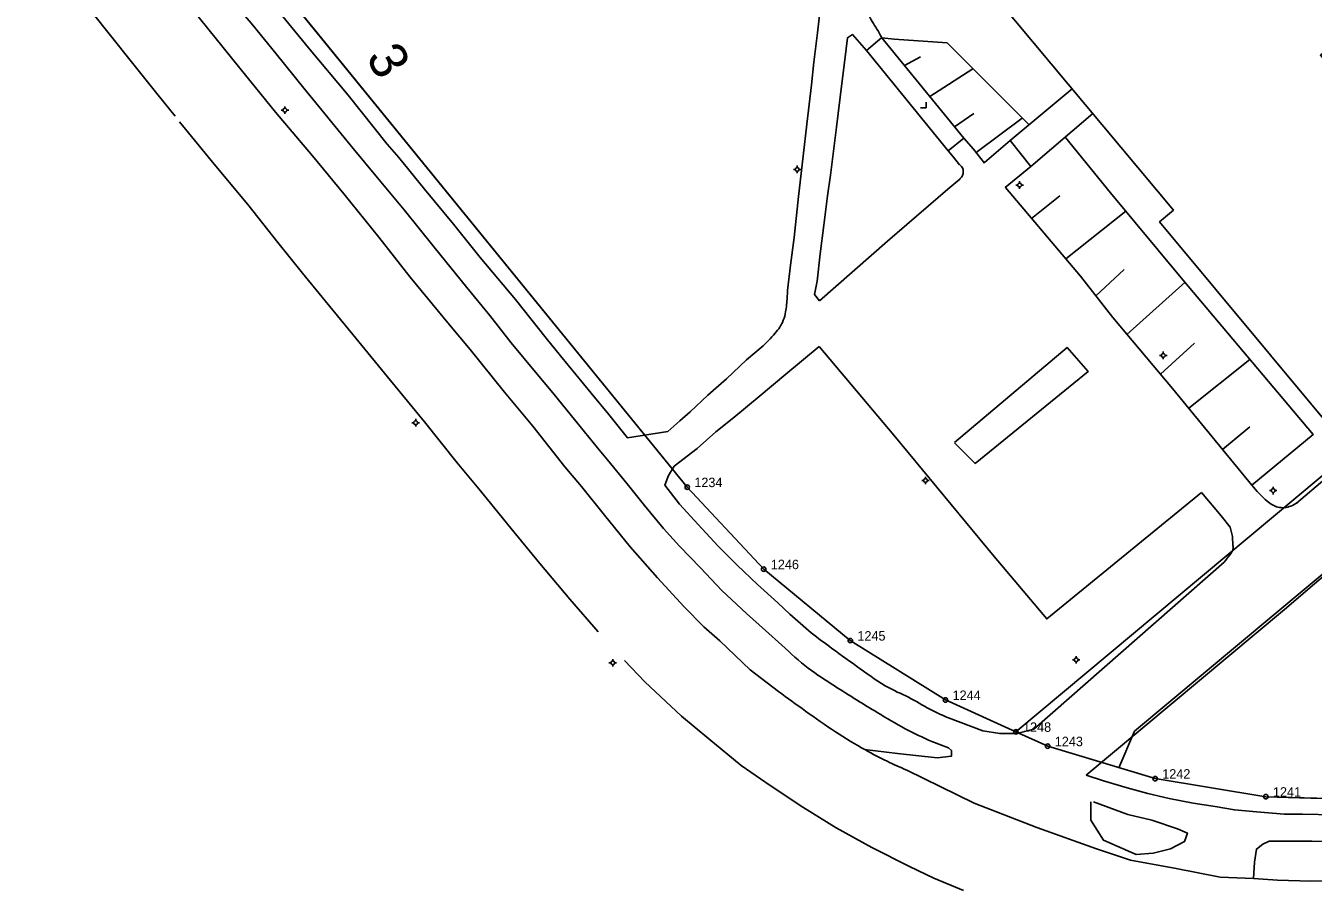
# Model space of a CAD drawing. Extents: x 1517693 to 1518189, y 6494860 to 6495280.
# Drawn here: x 1517702.4 to 1517838.6, y 6494947.3 to 6495038.2 of the extents above; entities that cross this region are included whole.
import ezdxf

# ---------------------------------------------------------------- set-up
doc = ezdxf.new("R2010")
doc.units = 0
for name, color, linetype in [('adress', 7, 'Continuous'), ('allmanbyggnad', 7, 'Continuous'), ('bro', 7, 'Continuous'), ('gc_vag', 7, 'Continuous'), ('grans', 7, 'Continuous'), ('granspunkt', 7, 'Continuous'), ('granspunkt_text', 7, 'Continuous'), ('kvartersgrans', 7, 'Continuous'), ('parkeringskant', 7, 'Continuous'), ('rattighet_grans_ANV_EJ', 7, 'Continuous'), ('slant_skraffering', 7, 'Continuous'), ('slantfot', 7, 'Continuous'), ('stodmur', 7, 'Continuous'), ('stolpe_belysning', 7, 'Continuous'), ('trappa', 7, 'Continuous'), ('trappsymbol', 7, 'Continuous'), ('vagkant', 7, 'Continuous'), ('vagkant_mindre', 7, 'Continuous')]:
    doc.layers.add(name, color=color, linetype=linetype)

msp = doc.modelspace()

# ---------------------------------------------------------------- linework, layer by layer
at = {"layer": 'allmanbyggnad'}
msp.add_lwpolyline([(1517795.98, 6495052.03), (1517837.72, 6495086.69), (1517844.24, 6495078.9), (1517844.89, 6495079.4), (1517856.96, 6495064.93), (1517856.28, 6495064.33), (1517862.19, 6495057.11), (1517842.98, 6495041.23), (1517844.57, 6495039.29), (1517839.38, 6495035.07), (1517847.33, 6495025.71), (1517853.22, 6495030.6), (1517862.35, 6495019.75), (1517850.98, 6495010.13), (1517853.38, 6495007.24), (1517840.06, 6494996.19), (1517822.37, 6495017.44), (1517823.84, 6495018.69), (1517795.97, 6495052.03)], dxfattribs=at)
at = {"layer": 'bro'}
msp.add_lwpolyline([(1517813.13, 6495031.51), (1517806.55, 6495026.04), (1517808.74, 6495023.31), (1517815.3, 6495028.91)], dxfattribs=at)
at = {"layer": 'gc_vag'}
for p, q in [((1517782.84, 6495001.34), (1517786.35, 6495004.25)), ((1517783.24, 6494975.95), (1517782, 6494977.16))]:
    msp.add_line(p, q, dxfattribs=at)
for points in [[(1517737.05, 6495025.22), (1517731.83, 6495031.58), (1517728.92, 6495035.22), (1517726.43, 6495038.23), (1517723.49, 6495041.77), (1517721.14, 6495044.68)], [(1517740.66, 6495025.65), (1517736.52, 6495030.84), (1517732.32, 6495035.85), (1517728.5, 6495040.55), (1517724.81, 6495044.99)], [(1517786.9, 6495043.91), (1517786.54, 6495040.51), (1517786.18, 6495037.43), (1517785.79, 6495034.34), (1517785.53, 6495031.93)], [(1517791.38, 6495035.56), (1517789.88, 6495037.27), (1517789.36, 6495036.91), (1517789.08, 6495034.58), (1517788.74, 6495032.09)], [(1517785.53, 6495031.93), (1517785.06, 6495027.78), (1517784.67, 6495024.39), (1517784.16, 6495020.11)], [(1517788.74, 6495032.09), (1517788.2, 6495027.45), (1517787.55, 6495022.39), (1517787.24, 6495020.21)], [(1517801.66, 6495026.31), (1517802.68, 6495025.15), (1517803.84, 6495023.66)], [(1517753.76, 6495004.65), (1517751.53, 6495007.54), (1517749.08, 6495010.52), (1517745.64, 6495014.76), (1517742.46, 6495018.72), (1517739.62, 6495022.1), (1517737.05, 6495025.22)], [(1517757.49, 6495005.15), (1517754.23, 6495009.22), (1517750.51, 6495013.67), (1517747.68, 6495017.21), (1517744.59, 6495020.89), (1517741.9, 6495024.25), (1517740.66, 6495025.65)], [(1517801.2, 6495023.49), (1517800.55, 6495024.28), (1517800, 6495024.96)], [(1517784.16, 6495020.11), (1517783.72, 6495015.78), (1517783.33, 6495012.85), (1517782.99, 6495010.18), (1517782.96, 6495009.28)], [(1517787.24, 6495020.21), (1517786.85, 6495017.1), (1517786.46, 6495014.07), (1517786.15, 6495011.19), (1517785.87, 6495009.77), (1517786.38, 6495009.1)], [(1517760.6, 6494996.36), (1517758.17, 6494999.37), (1517756.35, 6495001.55), (1517753.76, 6495004.65)], [(1517780.43, 6495004.32), (1517778.67, 6495002.85), (1517776.54, 6495000.85), (1517774.58, 6494999.13), (1517772.72, 6494997.34), (1517771.6, 6494996.4), (1517770.34, 6494995.28), (1517766.07, 6494994.61), (1517764.1, 6494997.06), (1517762.25, 6494999.31), (1517758.99, 6495003.29), (1517757.49, 6495005.15)], [(1517777.33, 6494996.75), (1517780.01, 6494998.96), (1517782.84, 6495001.34)], [(1517778.68, 6494976.01), (1517776.07, 6494978.46), (1517773.82, 6494980.84), (1517771.58, 6494983.15), (1517769.9, 6494985.01), (1517767.87, 6494987.43), (1517766.05, 6494989.74), (1517763.98, 6494992.26), (1517762.92, 6494993.54), (1517760.6, 6494996.36)], [(1517782, 6494977.16), (1517779.85, 6494979.09), (1517777.68, 6494981.12), (1517775.68, 6494983.15), (1517773.54, 6494985.43), (1517771.58, 6494987.6), (1517770.04, 6494989.6), (1517770.43, 6494990.62), (1517771.02, 6494991.6), (1517773.44, 6494993.49), (1517775.43, 6494995.24), (1517777.33, 6494996.75)], [(1517782.42, 6494972.66), (1517780.67, 6494974.22), (1517778.68, 6494976.01)], [(1517800.05, 6494964.98), (1517803.66, 6494963.63), (1517805.46, 6494963.33), (1517807.27, 6494963.33), (1517809.07, 6494963.78)], [(1517798.28, 6494962.48), (1517800.05, 6494961.83), (1517800.35, 6494961.52), (1517800.35, 6494960.92), (1517798.85, 6494960.77), (1517794.64, 6494961.22), (1517791.15, 6494961.65)], [(1517821.11, 6494956.98), (1517818.95, 6494957.58), (1517816.43, 6494958.31), (1517814.6, 6494958.94)], [(1517834.33, 6494954.91), (1517832.63, 6494955.05), (1517830.29, 6494955.26), (1517828.25, 6494955.61), (1517825.91, 6494955.97), (1517823.39, 6494956.46), (1517821.11, 6494956.98)], [(1517815.39, 6494956.11), (1517819, 6494954.76), (1517821.55, 6494954.15), (1517824.26, 6494953.25), (1517825.31, 6494952.8), (1517825.01, 6494951.9), (1517823.51, 6494951.15), (1517821.7, 6494950.69), (1517819.9, 6494950.54), (1517816.44, 6494952.05), (1517815.09, 6494954.15), (1517815.09, 6494956.11)], [(1517862.88, 6494955.09), (1517860.81, 6494955.05), (1517858.46, 6494954.98), (1517854.75, 6494954.91), (1517851, 6494954.84), (1517847.43, 6494954.88), (1517844.03, 6494954.84), (1517840.85, 6494954.74), (1517837.48, 6494954.81), (1517835.56, 6494954.81), (1517834.33, 6494954.91)], [(1517832.31, 6494947.99), (1517832.41, 6494949.71), (1517832.62, 6494951.11), (1517833.29, 6494951.63), (1517833.95, 6494951.95), (1517838.47, 6494951.95), (1517843.09, 6494951.84), (1517849.01, 6494951.84), (1517853.81, 6494951.88)]]:
    msp.add_lwpolyline(points, dxfattribs=at)
for points in [[(1517790.03, 6495044.5), (1517790.5, 6495042.53), (1517791.07, 6495040.61), (1517791.75, 6495039.03), (1517792.7, 6495037.43), (1517792.99, 6495036.91)], [(1517801.22, 6495021.95), (1517801.47, 6495022.27), (1517801.59, 6495022.68), (1517801.55, 6495023.09), (1517801.19, 6495023.5)], [(1517782.96, 6495009.28), (1517782.77, 6495007.72), (1517782.46, 6495006.81), (1517782.2, 6495006.32), (1517781.68, 6495005.65), (1517780.98, 6495004.9), (1517780.43, 6495004.32)], [(1517783.24, 6494975.95), (1517785.52, 6494973.99), (1517787.71, 6494972.33), (1517790.68, 6494970.19), (1517793.75, 6494968.16), (1517796.09, 6494967.01), (1517798.33, 6494965.76), (1517800.05, 6494964.98)], [(1517782.42, 6494972.66), (1517785.21, 6494970.24), (1517787.97, 6494968.37), (1517790.36, 6494966.86), (1517792.5, 6494965.55), (1517795.47, 6494963.83), (1517798.28, 6494962.48)]]:
    msp.add_spline(points, degree=3, dxfattribs=at)
at = {"layer": 'grans'}
for p, q in [((1517807.17, 6494963.51), (1517919.72, 6495057.58)), ((1517718.21, 6495055.89), (1517772.4, 6494989.39)), ((1517772.4, 6494989.39), (1517780.49, 6494980.71)), ((1517780.49, 6494980.71), (1517789.65, 6494973.16)), ((1517789.65, 6494973.16), (1517799.72, 6494966.88)), ((1517799.72, 6494966.88), (1517807.17, 6494963.51)), ((1517807.17, 6494963.51), (1517810.53, 6494961.99)), ((1517810.53, 6494961.99), (1517821.9, 6494958.56)), ((1517821.9, 6494958.56), (1517833.61, 6494956.65)), ((1517833.61, 6494956.65), (1517845.48, 6494956.3))]:
    msp.add_line(p, q, dxfattribs=at)
at = {"layer": 'granspunkt'}
for centre in [(1517772.4, 6494989.39), (1517780.49, 6494980.71), (1517789.65, 6494973.16), (1517799.72, 6494966.88), (1517807.17, 6494963.51), (1517810.53, 6494961.99), (1517821.9, 6494958.56), (1517833.61, 6494956.65)]:
    msp.add_circle(centre, 0.237, dxfattribs=at)
at = {"layer": 'kvartersgrans'}
for points in [[(1517718.21, 6495055.89), (1517772.4, 6494989.39), (1517780.49, 6494980.71), (1517789.65, 6494973.16), (1517799.72, 6494966.88)], [(1517810.53, 6494961.99), (1517821.9, 6494958.56), (1517833.61, 6494956.65), (1517845.48, 6494956.3), (1517968.3, 6494960.82), (1517976.46, 6494961.8), (1517984.36, 6494964.1), (1517991.77, 6494967.66)], [(1517799.72, 6494966.88), (1517807.17, 6494963.51), (1517810.53, 6494961.99)]]:
    msp.add_lwpolyline(points, dxfattribs=at)
at = {"layer": 'parkeringskant'}
msp.add_line((1517806.06, 6495021.07), (1517813.99, 6495011.69), dxfattribs=at)
for points in [[(1517786.38, 6495009.1), (1517793.6, 6495015.42), (1517799.97, 6495020.92), (1517801.22, 6495021.95)], [(1517813.99, 6495011.69), (1517817.41, 6495007.33), (1517823.73, 6494999.82), (1517832.13, 6494989.6)], [(1517786.35, 6495004.25), (1517794.25, 6494994.89), (1517804.87, 6494982.04)], [(1517800.68, 6494994.11), (1517812.59, 6495004.17), (1517814.82, 6495001.63), (1517802.85, 6494991.89), (1517800.68, 6494994.06)], [(1517804.87, 6494982.04), (1517810.44, 6494975.45), (1517826.82, 6494988.83)]]:
    msp.add_lwpolyline(points, dxfattribs=at)
at = {"layer": 'rattighet_grans_ANV_EJ'}
for p, q in [((1517924.99, 6495051.56), (1517819.73, 6494963.58)), ((1517819.73, 6494963.58), (1517818.07, 6494959.71))]:
    msp.add_line(p, q, dxfattribs=at)
at = {"layer": 'slant_skraffering'}
for p, q in [((1517795.39, 6495033.98), (1517797.09, 6495034.91)), ((1517798.06, 6495030.71), (1517802.63, 6495033.63)), ((1517800.68, 6495027.51), (1517802.71, 6495028.92)), ((1517802.97, 6495024.77), (1517807.84, 6495028.42)), ((1517808.82, 6495017.81), (1517811.81, 6495020.18)), ((1517812.44, 6495013.52), (1517818.8, 6495018.56)), ((1517815.62, 6495009.62), (1517818.63, 6495012.39)), ((1517818.92, 6495005.54), (1517825.06, 6495011.05)), ((1517822.47, 6495001.32), (1517826.05, 6495004.61)), ((1517825.45, 6494997.73), (1517831.92, 6495002.89)), ((1517829.03, 6494993.38), (1517831.92, 6494995.75))]:
    msp.add_line(p, q, dxfattribs=at)
at = {"layer": 'slantfot'}
for points in [[(1517792.98, 6495036.92), (1517794.29, 6495036.76), (1517799.9, 6495036.37), (1517808.6, 6495027.66)], [(1517824.82, 6495011.33), (1517817.18, 6495020.5), (1517812.41, 6495026.36)], [(1517832.13, 6494989.6), (1517838.61, 6494994.94), (1517824.82, 6495011.33)]]:
    msp.add_lwpolyline(points, dxfattribs=at)
at = {"layer": 'stodmur'}
for p, q in [((1517806.55, 6495026.04), (1517803.85, 6495023.73)), ((1517808.74, 6495023.31), (1517806.04, 6495021.07))]:
    msp.add_line(p, q, dxfattribs=at)
at = {"layer": 'stolpe_belysning'}
for p, q in [((1517729.64, 6495029.26), (1517729.44, 6495029.26)), ((1517729.84, 6495029.46), (1517729.84, 6495029.66)), ((1517729.84, 6495029.06), (1517729.84, 6495028.86)), ((1517730.04, 6495029.26), (1517730.24, 6495029.26)), ((1517784.03, 6495023.19), (1517784.03, 6495023.39)), ((1517783.83, 6495022.99), (1517783.63, 6495022.99)), ((1517784.03, 6495022.79), (1517784.03, 6495022.59)), ((1517784.23, 6495022.99), (1517784.43, 6495022.99)), ((1517807.36, 6495021.34), (1517807.16, 6495021.34)), ((1517807.56, 6495021.54), (1517807.56, 6495021.74)), ((1517807.56, 6495021.14), (1517807.56, 6495020.94)), ((1517807.76, 6495021.34), (1517807.96, 6495021.34)), ((1517822.56, 6495003.32), (1517822.36, 6495003.32)), ((1517822.76, 6495003.52), (1517822.76, 6495003.72)), ((1517822.76, 6495003.12), (1517822.76, 6495002.92)), ((1517822.96, 6495003.32), (1517823.16, 6495003.32)), ((1517743.47, 6494996.2), (1517743.27, 6494996.2)), ((1517743.67, 6494996.4), (1517743.67, 6494996.6)), ((1517743.87, 6494996.2), (1517744.07, 6494996.2)), ((1517743.67, 6494996), (1517743.67, 6494995.8)), ((1517797.4, 6494990.09), (1517797.2, 6494990.09)), ((1517797.6, 6494990.29), (1517797.6, 6494990.49)), ((1517797.6, 6494989.89), (1517797.6, 6494989.69)), ((1517797.8, 6494990.09), (1517798, 6494990.09)), ((1517834.38, 6494989.22), (1517834.38, 6494989.42)), ((1517834.18, 6494989.02), (1517833.98, 6494989.02)), ((1517834.38, 6494988.82), (1517834.38, 6494988.62)), ((1517834.58, 6494989.02), (1517834.78, 6494989.02)), ((1517813.54, 6494971.32), (1517813.54, 6494971.52)), ((1517764.32, 6494970.81), (1517764.12, 6494970.81)), ((1517764.52, 6494971.01), (1517764.52, 6494971.21)), ((1517764.52, 6494970.61), (1517764.52, 6494970.41)), ((1517764.72, 6494970.81), (1517764.92, 6494970.81)), ((1517813.34, 6494971.12), (1517813.14, 6494971.12)), ((1517813.54, 6494970.92), (1517813.54, 6494970.72)), ((1517813.74, 6494971.12), (1517813.94, 6494971.12))]:
    msp.add_line(p, q, dxfattribs=at)
for centre in [(1517729.84, 6495029.26), (1517784.03, 6495022.99), (1517807.56, 6495021.34), (1517822.76, 6495003.32), (1517743.67, 6494996.2), (1517797.6, 6494990.09), (1517834.38, 6494989.02), (1517764.52, 6494970.81), (1517813.54, 6494971.12)]:
    msp.add_circle(centre, 0.2, dxfattribs=at)
at = {"layer": 'trappa'}
msp.add_lwpolyline([(1517791.38, 6495035.56), (1517793, 6495036.93), (1517792.99, 6495036.91), (1517801.66, 6495026.31), (1517800, 6495024.96), (1517791.38, 6495035.56)], dxfattribs=at)
at = {"layer": 'trappsymbol'}
msp.add_lwpolyline([(1517797.07, 6495029.52), (1517797.67, 6495029.52), (1517797.67, 6495030.12)], dxfattribs=at)
at = {"layer": 'vagkant'}
for points in [[(1517718.21, 6495028.61), (1517716.29, 6495031.02), (1517713.45, 6495034.56), (1517709.43, 6495039.57), (1517705.29, 6495044.58), (1517702.42, 6495048.15)], [(1517728.85, 6495029.05), (1517725.08, 6495033.71), (1517719.93, 6495040.09), (1517718.21, 6495042.23)], [(1517743.08, 6495011.6), (1517739.78, 6495015.81), (1517736.06, 6495020.4), (1517732.74, 6495024.43), (1517728.85, 6495029.05)], [(1517731.71, 6495012.01), (1517729.09, 6495015.25), (1517725.91, 6495019.28), (1517722.37, 6495023.55), (1517718.67, 6495028.03)], [(1517748.05, 6494991.95), (1517744.59, 6494996.29), (1517740.99, 6495000.67), (1517737.34, 6495005.16), (1517733.77, 6495009.47), (1517731.71, 6495012.01)], [(1517759.46, 6494991.53), (1517756.05, 6494995.84), (1517753.07, 6494999.45), (1517749.43, 6495003.93), (1517747.24, 6495006.57), (1517743.08, 6495011.6)], [(1517762.98, 6494974.08), (1517759.97, 6494977.55), (1517756.82, 6494981.33), (1517753.74, 6494985.04), (1517750.34, 6494989.21), (1517748.05, 6494991.95)], [(1517774.16, 6494974.6), (1517772.06, 6494976.74), (1517769.25, 6494979.79), (1517766.35, 6494983.08), (1517763.65, 6494986.41), (1517761.2, 6494989.46), (1517759.46, 6494991.53)], [(1517782.06, 6494967.77), (1517779.06, 6494970.05), (1517775.84, 6494973.13), (1517774.16, 6494974.6)], [(1517778.12, 6494959.96), (1517774.68, 6494962.76), (1517771.81, 6494965.18), (1517767.91, 6494968.78), (1517765.76, 6494971.04)], [(1517801.64, 6494946.72), (1517798.5, 6494948.05), (1517795.91, 6494949.27), (1517791.92, 6494951.27), (1517788.17, 6494953.37), (1517784.63, 6494955.54), (1517781.16, 6494957.82), (1517778.12, 6494959.96)], [(1517795.62, 6494959.46), (1517802.76, 6494955.96), (1517809.37, 6494953.4), (1517815.69, 6494951.15), (1517819.3, 6494949.94), (1517824.11, 6494949.04), (1517828.77, 6494948.14), (1517832.31, 6494947.99)], [(1517832.31, 6494947.99), (1517834.83, 6494947.82), (1517838.37, 6494947.71), (1517842.24, 6494947.74), (1517847.89, 6494947.75), (1517851.78, 6494947.96), (1517854.13, 6494948.06)]]:
    msp.add_lwpolyline(points, dxfattribs=at)
msp.add_spline([(1517782.06, 6494967.77), (1517784.9, 6494965.71), (1517788.07, 6494963.52), (1517791.25, 6494961.59), (1517793.54, 6494960.39), (1517795.62, 6494959.46)], degree=3, dxfattribs=at)
at = {"layer": 'vagkant_mindre'}
msp.add_line((1517809.07, 6494963.78), (1517829.2, 6494981.47), dxfattribs=at)
for points in [[(1517814.6, 6494958.94), (1517835.57, 6494976.43), (1517848.02, 6494987.1), (1517878.6, 6495013.87), (1517874.09, 6495020.04)], [(1517836.85, 6494987.68), (1517842.85, 6494992.77), (1517840.06, 6494996.19)], [(1517826.82, 6494988.83), (1517828.89, 6494986.34), (1517829.82, 6494985.15), (1517830.08, 6494984.16), (1517830.13, 6494983.23)]]:
    msp.add_lwpolyline(points, dxfattribs=at)
for points in [[(1517832.13, 6494989.6), (1517833.76, 6494987.89), (1517834.9, 6494987.27), (1517836.25, 6494987.38), (1517836.97, 6494987.74)], [(1517830.13, 6494983.23), (1517830.13, 6494982.81), (1517829.84, 6494982.28), (1517829.2, 6494981.47)]]:
    msp.add_spline(points, degree=3, dxfattribs=at)

# ---------------------------------------------------------------- texts
at = {"layer": 'adress'}
msp.add_text('3', height=4, rotation=299.2317, dxfattribs=at).set_placement((1517738.35, 6495034.87))
at = {"layer": 'granspunkt_text'}
for s, p in [('1234', (1517773.15, 6494989.39)), ('1246', (1517781.24, 6494980.71)), ('1245', (1517790.4, 6494973.16)), ('1244', (1517800.47, 6494966.88)), ('1248', (1517807.92, 6494963.51)), ('1243', (1517811.28, 6494961.99)), ('1242', (1517822.65, 6494958.56)), ('1241', (1517834.36, 6494956.65))]:
    msp.add_text(s, height=1, dxfattribs=at).set_placement(p)

doc.saveas('drawing.dxf')
